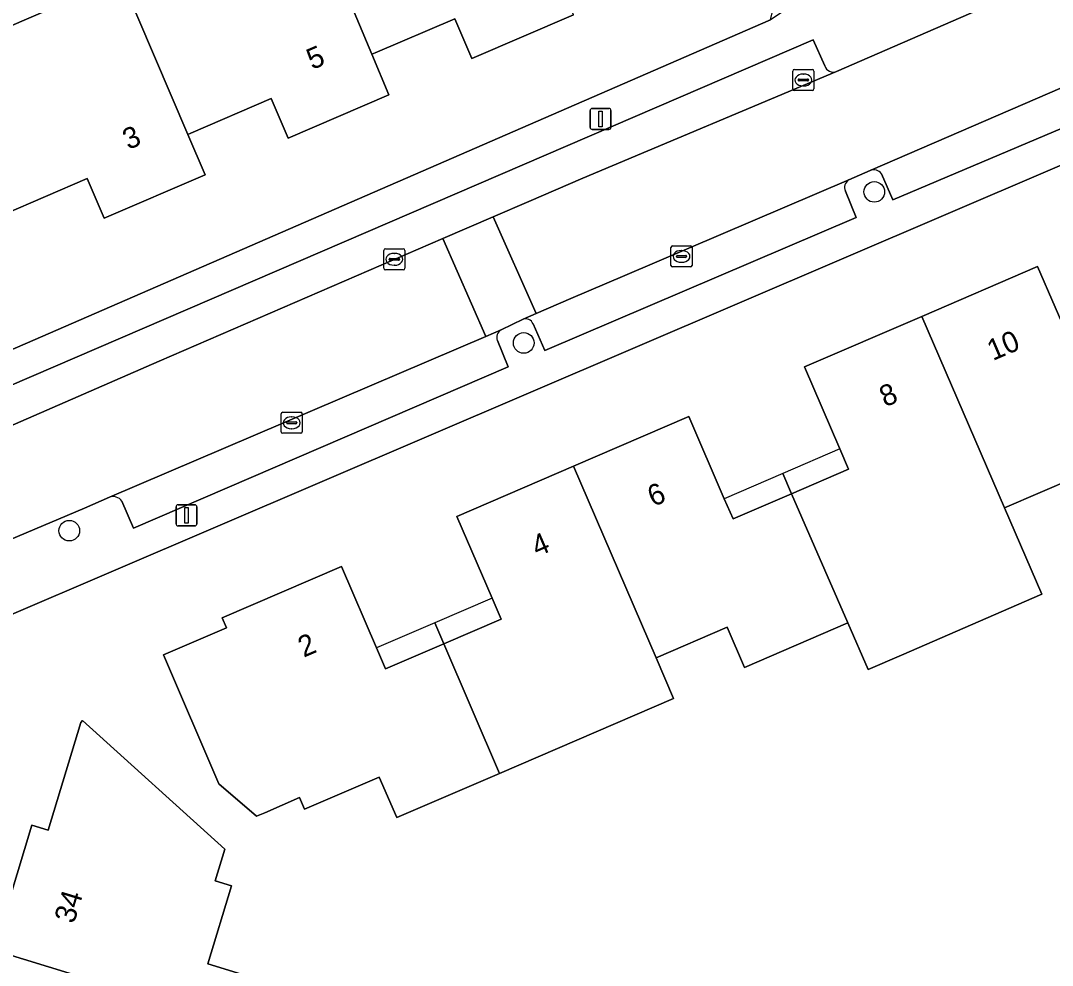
# Model space of a CAD drawing. Extents: x 157767 to 159172, y 387839 to 389425.
# Drawn here: x 158122.64 to 158171.64, y 388608.77 to 388653.65 of the extents above; entities that cross this region are included whole.
import ezdxf

# ---------------------------------------------------------------- set-up
doc = ezdxf.new("R2010")
doc.units = 0
for name, color, linetype in [('IMGEO_Boom', 7, 'Continuous'), ('IMGEO_Erf', 7, 'Continuous'), ('IMGEO_Kolk', 7, 'Continuous'), ('IMGEO_Lichtmast', 7, 'Continuous'), ('IMGEO_Pand', 7, 'Continuous'), ('IMGEO_Pand_nummerreeks', 7, 'Continuous'), ('IMGEO_Pand_overbouw', 7, 'Continuous'), ('IMGEO_Parkeervlak_open', 7, 'Continuous'), ('IMGEO_Rijbaan_lokaal_open', 7, 'Continuous'), ('IMGEO_Voetpad_open', 7, 'Continuous')]:
    doc.layers.add(name, color=color, linetype=linetype)

msp = doc.modelspace()

# ---------------------------------------------------------------- linework, layer by layer
at = {"layer": 'IMGEO_Boom'}
for centre in [(158163.181, 388645.511), (158146.533, 388638.337), (158124.95, 388629.419)]:
    msp.add_circle(centre, 0.489, dxfattribs=at)
at = {"layer": 'IMGEO_Erf'}
for points in [[(158084.381, 388632.682), (158087.009, 388632.342), (158090.303, 388632.39), (158090.684, 388632.396), (158089.16, 388634.912), (158092.905, 388637.179), (158094.487, 388634.565), (158090.907, 388632.399), (158106.724, 388632.63), (158109.87, 388633.38), (158113.99, 388634.449), (158158.26, 388653.682), (158159.32, 388658.046), (158157.478, 388662.318), (158148.912, 388682.181)], [(158206.335, 388661.478), (158121.982, 388625.344), (158121.909, 388625.102), (158108.361, 388580.257)], [(158121.543, 388653.132), (158127.411, 388655.659)], [(158148.894, 388653.918), (158144.073, 388651.843), (158143.257, 388653.738), (158139.473, 388652.109), (158139.325, 388652.046), (158140.133, 388650.121), (158135.35, 388648.061), (158134.538, 388649.946), (158130.727, 388648.306), (158130.576, 388648.241), (158131.397, 388646.318), (158126.612, 388644.258), (158125.8, 388646.144), (158121.836, 388644.437)], [(158172.748, 388631.966), (158169.362, 388630.508), (158171.136, 388626.404), (158164.48, 388623.513), (158162.887, 388622.821), (158161.924, 388625.036), (158157.017, 388622.923), (158156.192, 388624.837), (158152.815, 388623.383), (158153.647, 388621.452), (158145.377, 388617.891), (158140.501, 388615.791), (158139.673, 388617.715), (158136.125, 388616.187), (158135.888, 388616.738), (158134.231, 388616.025), (158133.849, 388615.86), (158132.056, 388617.394), (158129.418, 388623.52), (158132.412, 388624.81), (158132.208, 388625.284), (158137.873, 388627.723), (158139.54, 388623.851), (158139.969, 388622.855), (158142.732, 388624.045), (158145.459, 388625.219), (158145.03, 388626.215), (158143.358, 388630.097), (158148.896, 388632.482), (158154.375, 388634.842), (158156.057, 388630.939), (158156.472, 388629.975), (158159.255, 388631.174), (158161.956, 388632.337), (158161.541, 388633.3), (158159.864, 388637.194), (158165.435, 388639.593), (158170.94, 388641.963), (158172.604, 388638.102)], [(158125.364, 388608.277), (158121.373, 388609.487), (158123.177, 388615.431), (158123.945, 388615.198), (158125.498, 388620.309), (158125.578, 388620.401), (158132.331, 388614.286), (158131.877, 388612.79), (158132.654, 388612.554), (158131.528, 388608.844), (158133.533, 388608.235)]]:
    msp.add_lwpolyline(points, dxfattribs=at)
at = {"layer": 'IMGEO_Kolk'}
for p, q in [((158159.387, 388651.326), (158160.239, 388651.326)), ((158159.312, 388650.4), (158159.312, 388651.252)), ((158159.571, 388650.82), (158159.571, 388650.832)), ((158160.009, 388650.783), (158159.611, 388650.783)), ((158159.614, 388650.869), (158160.012, 388650.869)), ((158159.8, 388651.106), (158159.825, 388651.106)), ((158160.055, 388650.832), (158160.055, 388650.82)), ((158160.313, 388651.252), (158160.313, 388650.4)), ((158160.239, 388650.326), (158159.387, 388650.326)), ((158159.823, 388650.546), (158159.798, 388650.546)), ((158153.601, 388642.945), (158154.453, 388642.945)), ((158139.886, 388641.882), (158139.886, 388642.734)), ((158139.961, 388642.808), (158140.813, 388642.808)), ((158140.374, 388642.588), (158140.399, 388642.588)), ((158140.887, 388642.734), (158140.887, 388641.882)), ((158153.526, 388642.019), (158153.526, 388642.871)), ((158153.785, 388642.439), (158153.785, 388642.451)), ((158153.828, 388642.488), (158154.226, 388642.488)), ((158154.014, 388642.725), (158154.039, 388642.725)), ((158154.269, 388642.451), (158154.269, 388642.439)), ((158154.527, 388642.871), (158154.527, 388642.019)), ((158140.145, 388642.302), (158140.145, 388642.314)), ((158140.583, 388642.265), (158140.185, 388642.265)), ((158140.188, 388642.351), (158140.586, 388642.351)), ((158140.397, 388642.028), (158140.372, 388642.028)), ((158140.629, 388642.314), (158140.629, 388642.302)), ((158154.223, 388642.402), (158153.825, 388642.402)), ((158154.037, 388642.165), (158154.012, 388642.165)), ((158140.813, 388641.808), (158139.961, 388641.808)), ((158154.453, 388641.945), (158153.601, 388641.945)), ((158135.012, 388634.118), (158135.012, 388634.97)), ((158135.087, 388635.044), (158135.939, 388635.044)), ((158135.5, 388634.824), (158135.525, 388634.824)), ((158136.013, 388634.97), (158136.013, 388634.118)), ((158135.271, 388634.538), (158135.271, 388634.55)), ((158135.709, 388634.501), (158135.311, 388634.501)), ((158135.314, 388634.587), (158135.712, 388634.587)), ((158135.523, 388634.264), (158135.498, 388634.264)), ((158135.755, 388634.55), (158135.755, 388634.538)), ((158135.939, 388634.044), (158135.087, 388634.044))]:
    msp.add_line(p, q, dxfattribs=at)
for points in [[(158159.387, 388651.326), (158160.239, 388651.326)], [(158159.312, 388650.4), (158159.312, 388651.252)], [(158160.313, 388651.252), (158160.313, 388650.4)], [(158160.239, 388650.326), (158159.387, 388650.326)], [(158153.601, 388642.945), (158154.453, 388642.945)], [(158139.886, 388641.882), (158139.886, 388642.734)], [(158139.961, 388642.808), (158140.813, 388642.808)], [(158140.887, 388642.734), (158140.887, 388641.882)], [(158153.526, 388642.019), (158153.526, 388642.871)], [(158154.527, 388642.871), (158154.527, 388642.019)], [(158140.813, 388641.808), (158139.961, 388641.808)], [(158154.453, 388641.945), (158153.601, 388641.945)], [(158135.012, 388634.118), (158135.012, 388634.97)], [(158135.087, 388635.044), (158135.939, 388635.044)], [(158136.013, 388634.97), (158136.013, 388634.118)], [(158135.939, 388634.044), (158135.087, 388634.044)]]:
    msp.add_lwpolyline(points, dxfattribs=at)
for centre, radius, start, end in [((158159.389, 388651.25), 0.0765, 91.552, 178.448), ((158159.389, 388651.25), 0.0765, 91.552, 178.448), ((158160.237, 388651.25), 0.0765, 1.552, 88.448), ((158160.237, 388651.25), 0.0765, 1.552, 88.448), ((158159.611, 388650.829), 0.0403, 85.8775, 175.7526), ((158159.608, 388650.819), 0.0366, 178.938, 274.7102), ((158160.012, 388650.826), 0.043, 264.8664, 352.4533), ((158160.016, 388650.831), 0.0386, 1.7309, 96.639), ((158159.389, 388650.402), 0.0765, 181.552, 268.448), ((158159.389, 388650.402), 0.0765, 181.552, 268.448), ((158160.237, 388650.402), 0.0765, 271.552, 358.448), ((158160.237, 388650.402), 0.0765, 271.552, 358.448), ((158153.603, 388642.869), 0.0765, 91.552, 178.448), ((158153.603, 388642.869), 0.0765, 91.552, 178.448), ((158154.451, 388642.869), 0.0765, 1.552, 88.448), ((158154.451, 388642.869), 0.0765, 1.552, 88.448), ((158139.963, 388642.732), 0.0765, 91.552, 178.448), ((158139.963, 388642.732), 0.0765, 91.552, 178.448), ((158140.811, 388642.732), 0.0765, 1.552, 88.448), ((158140.811, 388642.732), 0.0765, 1.552, 88.448), ((158153.825, 388642.448), 0.0403, 85.8775, 175.7526), ((158154.23, 388642.45), 0.0386, 1.7309, 96.639), ((158140.185, 388642.311), 0.0403, 85.8775, 175.7526), ((158140.182, 388642.301), 0.0366, 178.938, 274.7102), ((158140.586, 388642.308), 0.043, 264.8664, 352.4533), ((158140.59, 388642.313), 0.0386, 1.7309, 96.639), ((158153.603, 388642.021), 0.0765, 181.552, 268.448), ((158153.603, 388642.021), 0.0765, 181.552, 268.448), ((158153.822, 388642.438), 0.0366, 178.938, 274.7102), ((158154.226, 388642.445), 0.043, 264.8664, 352.4533), ((158154.451, 388642.021), 0.0765, 271.552, 358.448), ((158154.451, 388642.021), 0.0765, 271.552, 358.448), ((158139.963, 388641.884), 0.0765, 181.552, 268.448), ((158139.963, 388641.884), 0.0765, 181.552, 268.448), ((158140.811, 388641.884), 0.0765, 271.552, 358.448), ((158140.811, 388641.884), 0.0765, 271.552, 358.448), ((158135.089, 388634.968), 0.0765, 91.552, 178.448), ((158135.089, 388634.968), 0.0765, 91.552, 178.448), ((158135.937, 388634.968), 0.0765, 1.552, 88.448), ((158135.937, 388634.968), 0.0765, 1.552, 88.448), ((158135.089, 388634.12), 0.0765, 181.552, 268.448), ((158135.089, 388634.12), 0.0765, 181.552, 268.448), ((158135.311, 388634.547), 0.0403, 85.8775, 175.7526), ((158135.308, 388634.537), 0.0366, 178.938, 274.7102), ((158135.712, 388634.544), 0.043, 264.8664, 352.4533), ((158135.716, 388634.549), 0.0386, 1.7309, 96.639), ((158135.937, 388634.12), 0.0765, 271.552, 358.448), ((158135.937, 388634.12), 0.0765, 271.552, 358.448)]:
    msp.add_arc(centre, radius, start, end, dxfattribs=at)
for centre, major_axis, ratio, start_param, end_param in [((158159.799, 388650.826), (-0.387, 0.002), 0.722429, 4.712389, 7.853982), ((158159.824, 388650.826), (-0.39, 0.002), 0.717154, 1.570796, 4.712389), ((158140.373, 388642.308), (-0.387, 0.002), 0.722429, 4.712389, 7.853982), ((158140.398, 388642.308), (-0.39, 0.002), 0.717154, 1.570796, 4.712389), ((158154.013, 388642.445), (-0.387, 0.002), 0.722429, 4.712389, 7.853982), ((158154.038, 388642.445), (-0.39, 0.002), 0.717154, 1.570796, 4.712389), ((158135.499, 388634.544), (-0.387, 0.002), 0.722429, 4.712389, 7.853982), ((158135.524, 388634.544), (-0.39, 0.002), 0.717154, 1.570796, 4.712389)]:
    msp.add_ellipse(centre, major_axis=major_axis, ratio=ratio, start_param=start_param, end_param=end_param, dxfattribs=at)
at = {"layer": 'IMGEO_Lichtmast'}
for p, q in [((158149.685, 388648.576), (158149.685, 388649.376)), ((158149.685, 388649.376), (158149.685, 388648.576)), ((158149.785, 388649.476), (158150.575, 388649.476)), ((158150.575, 388649.476), (158149.785, 388649.476)), ((158150.675, 388649.376), (158150.675, 388648.576)), ((158150.675, 388648.576), (158150.675, 388649.376)), ((158150.575, 388648.476), (158149.785, 388648.476)), ((158149.785, 388648.476), (158150.575, 388648.476)), ((158130.019, 388629.749), (158130.019, 388630.549)), ((158130.019, 388630.549), (158130.019, 388629.749)), ((158130.119, 388630.649), (158130.909, 388630.649)), ((158130.909, 388630.649), (158130.119, 388630.649)), ((158131.009, 388630.549), (158131.009, 388629.749)), ((158131.009, 388629.749), (158131.009, 388630.549)), ((158130.909, 388629.649), (158130.119, 388629.649)), ((158130.119, 388629.649), (158130.909, 388629.649))]:
    msp.add_line(p, q, dxfattribs=at)
for points in [[(158150.105, 388649.351), (158150.255, 388649.351), (158150.255, 388648.601), (158150.105, 388648.601), (158150.105, 388649.351)], [(158130.439, 388630.524), (158130.589, 388630.524), (158130.589, 388629.774), (158130.439, 388629.774), (158130.439, 388630.524)]]:
    msp.add_lwpolyline(points, dxfattribs=at)
for centre, start, end in [((158149.785, 388649.376), 90, 180), ((158149.785, 388649.376), 90, 180), ((158150.575, 388649.376), 0, 90), ((158150.575, 388649.376), 360, 90), ((158149.785, 388648.576), 180, 270), ((158149.785, 388648.576), 180, 270), ((158150.575, 388648.576), 270, 0), ((158150.575, 388648.576), 270, 0), ((158130.119, 388630.549), 90, 180), ((158130.119, 388630.549), 90, 180), ((158130.909, 388630.549), 0, 90), ((158130.909, 388630.549), 360, 90), ((158130.119, 388629.749), 180, 270), ((158130.119, 388629.749), 180, 270), ((158130.909, 388629.749), 270, 0), ((158130.909, 388629.749), 270, 0)]:
    msp.add_arc(centre, 0.1, start, end, dxfattribs=at)
at = {"layer": 'IMGEO_Pand'}
for points in [[(158144.937, 388663.207), (158144.815, 388663.154), (158136.218, 388659.452), (158139.325, 388652.046), (158139.473, 388652.109), (158143.257, 388653.738), (158144.073, 388651.843), (158148.894, 388653.918), (158147.692, 388656.739)], [(158136.218, 388659.452), (158127.411, 388655.659), (158130.576, 388648.241), (158130.727, 388648.306), (158134.538, 388649.946), (158135.35, 388648.061), (158140.133, 388650.121), (158139.325, 388652.046)], [(158127.411, 388655.659), (158121.543, 388653.132), (158120.609, 388655.302), (158119.782, 388655.664), (158117.538, 388654.697), (158117.42, 388654.646), (158118.623, 388651.875), (158121.836, 388644.437), (158125.8, 388646.144), (158126.612, 388644.258), (158131.397, 388646.318), (158130.576, 388648.241)], [(158175.82, 388638.295), (158173.038, 388637.096), (158172.604, 388638.102), (158170.94, 388641.963), (158165.435, 388639.593), (158169.362, 388630.508), (158172.748, 388631.966), (158173.57, 388630.056), (158178.445, 388632.155)], [(158165.435, 388639.593), (158159.864, 388637.194), (158161.541, 388633.3), (158161.956, 388632.337), (158159.255, 388631.174), (158161.924, 388625.036), (158162.887, 388622.821), (158164.48, 388623.513), (158171.136, 388626.404), (158169.362, 388630.508)], [(158159.255, 388631.174), (158156.472, 388629.975), (158156.057, 388630.939), (158154.375, 388634.842), (158148.896, 388632.482), (158152.815, 388623.383), (158156.192, 388624.837), (158157.017, 388622.923), (158161.924, 388625.036)], [(158148.896, 388632.482), (158143.358, 388630.097), (158145.03, 388626.215), (158145.459, 388625.219), (158142.732, 388624.045), (158145.377, 388617.891), (158153.647, 388621.452), (158152.815, 388623.383)], [(158142.732, 388624.045), (158139.969, 388622.855), (158139.54, 388623.851), (158137.873, 388627.723), (158132.208, 388625.284), (158132.412, 388624.81), (158129.418, 388623.52), (158132.056, 388617.394), (158133.849, 388615.86), (158134.231, 388616.025), (158135.888, 388616.738), (158136.125, 388616.187), (158139.673, 388617.715), (158140.501, 388615.791), (158145.377, 388617.891)], [(158132.654, 388612.554), (158131.877, 388612.79), (158132.331, 388614.286), (158125.578, 388620.401), (158125.498, 388620.309), (158123.945, 388615.198), (158123.177, 388615.431), (158121.373, 388609.487), (158125.364, 388608.277), (158126.349, 388607.978), (158125.508, 388605.204), (158132.014, 388603.229), (158132.651, 388605.327), (158133.533, 388608.235), (158131.528, 388608.844)]]:
    msp.add_lwpolyline(points, close=True, dxfattribs=at)
at = {"layer": 'IMGEO_Pand_overbouw'}
for points in [[(158159.255, 388631.174), (158161.956, 388632.337), (158161.541, 388633.3), (158158.84, 388632.137)], [(158159.255, 388631.174), (158158.84, 388632.137), (158156.057, 388630.939), (158156.472, 388629.975)], [(158142.732, 388624.045), (158145.459, 388625.219), (158145.03, 388626.215), (158142.304, 388625.041)], [(158142.732, 388624.045), (158142.304, 388625.041), (158139.54, 388623.851), (158139.969, 388622.855)]]:
    msp.add_lwpolyline(points, close=True, dxfattribs=at)
at = {"layer": 'IMGEO_Parkeervlak_open'}
for points in [[(158179.359, 388653.609), (158162.981, 388646.531)], [(158160.827, 388651.496), (158160.285, 388652.739), (158119.94, 388635.358), (158120.458, 388634.115)], [(158163.531, 388646.37), (158164.067, 388645.127), (158179.732, 388651.775)], [(158142.689, 388643.29), (158145.081, 388644.324), (158146.782, 388645.058), (158149.334, 388646.16), (158161.392, 388651.228)], [(158161.979, 388646.076), (158151.329, 388641.544), (158148.776, 388640.444), (158147.13, 388639.735), (158146.498, 388639.462)], [(158162.327, 388644.294), (158161.814, 388645.55)], [(158146.976, 388639.246), (158147.541, 388637.974), (158162.327, 388644.294)], [(158120.282, 388633.571), (158129.222, 388637.475), (158142.689, 388643.29)], [(158145.455, 388638.953), (158144.74, 388638.648), (158126.853, 388631.015)], [(158145.797, 388637.197), (158145.28, 388638.45)], [(158127.447, 388630.817), (158128, 388629.538), (158145.797, 388637.197)]]:
    msp.add_lwpolyline(points, dxfattribs=at)
for centre, radius, start, end in [((158161.234, 388651.624), 0.426, 197.4318, 291.8148), ((158163.146, 388646.076), 0.484, 37.4206, 109.9471), ((158162.164, 388645.729), 0.393, 118.0272, 207.1408), ((158146.615, 388639.084), 0.396, 24.2009, 107.1643), ((158145.67, 388638.596), 0.417, 121.1048, 200.5283), ((158127.02, 388630.526), 0.517, 34.2687, 108.8614)]:
    msp.add_arc(centre, radius, start, end, dxfattribs=at)
at = {"layer": 'IMGEO_Rijbaan_lokaal_open'}
for points in [[(158179.359, 388653.609), (158180.27, 388653.992), (158190.897, 388658.576), (158191.881, 388659.026), (158193.866, 388659.878), (158191.878, 388664.469), (158171.987, 388655.85), (158161.392, 388651.228), (158149.334, 388646.16), (158146.782, 388645.058), (158145.081, 388644.324), (158147.13, 388639.735), (158148.776, 388640.444), (158151.329, 388641.544), (158161.979, 388646.076), (158162.981, 388646.531)], [(158145.081, 388644.324), (158142.689, 388643.29), (158144.74, 388638.648), (158145.455, 388638.953), (158146.498, 388639.462), (158147.13, 388639.735)]]:
    msp.add_lwpolyline(points, close=True, dxfattribs=at)
for points in [[(158144.74, 388638.648), (158142.689, 388643.29), (158129.222, 388637.475), (158120.282, 388633.571), (158118.807, 388633.004), (158116.61, 388632.148), (158114.663, 388631.608)], [(158120.299, 388628.215), (158122.493, 388629.144), (158125.679, 388630.492), (158126.853, 388631.015), (158144.74, 388638.648)]]:
    msp.add_lwpolyline(points, dxfattribs=at)
at = {"layer": 'IMGEO_Voetpad_open'}
for points in [[(158297.552, 388713.441), (158293.914, 388712.06), (158281.335, 388706.644), (158265.791, 388699.949), (158226.572, 388683.059), (158223.84, 388681.871), (158171.568, 388659.372), (158166.983, 388658.516), (158164.943, 388657.643), (158162.824, 388656.737), (158158.26, 388653.682), (158113.99, 388634.449), (158109.87, 388633.38), (158106.724, 388632.63), (158090.907, 388632.399), (158090.742, 388632.299), (158090.684, 388632.396), (158090.303, 388632.39), (158087.009, 388632.342), (158084.381, 388632.682), (158084.562, 388631.046)], [(158121.982, 388625.344), (158206.335, 388661.478)], [(158161.392, 388651.228), (158171.987, 388655.85)], [(158120.458, 388634.115), (158119.94, 388635.358), (158160.285, 388652.739), (158160.827, 388651.496)], [(158179.191, 388653.042), (158179.732, 388651.775), (158164.067, 388645.127), (158163.531, 388646.37)], [(158162.981, 388646.531), (158161.979, 388646.076)], [(158161.814, 388645.55), (158162.327, 388644.294), (158147.541, 388637.974), (158146.976, 388639.246)], [(158146.498, 388639.462), (158145.455, 388638.953)], [(158145.28, 388638.45), (158145.797, 388637.197), (158128, 388629.538), (158127.447, 388630.817)], [(158126.853, 388631.015), (158125.679, 388630.492), (158122.493, 388629.144), (158120.299, 388628.215)]]:
    msp.add_lwpolyline(points, dxfattribs=at)
for centre, radius, start, end in [((158161.234, 388651.624), 0.426, 197.4318, 291.8148), ((158163.146, 388646.076), 0.484, 37.4206, 109.9471), ((158162.164, 388645.729), 0.393, 118.0272, 207.1408), ((158146.615, 388639.084), 0.396, 24.2009, 107.1643), ((158145.67, 388638.596), 0.417, 121.1048, 200.5283), ((158127.02, 388630.526), 0.517, 34.2687, 108.8614)]:
    msp.add_arc(centre, radius, start, end, dxfattribs=at)

# ---------------------------------------------------------------- texts
at = {"layer": 'IMGEO_Pand_nummerreeks'}
for s, rotation, p in [('5', 23.3022, (158136.492, 388651.296)), ('3', 23.2907, (158127.756, 388647.494)), ('10', 23.2953, (158168.812, 388637.475)), ('8', 23.2965, (158163.698, 388635.273)), ('6', 23.3015, (158152.681, 388630.541)), ('4', 23.3022, (158147.172, 388628.168)), ('2', 23.2937, (158136.083, 388623.381)), ('34', 73.1151, (158125.173, 388610.716))]:
    msp.add_text(s, height=1, rotation=rotation, dxfattribs=at).set_placement(p)

doc.saveas('drawing.dxf')
